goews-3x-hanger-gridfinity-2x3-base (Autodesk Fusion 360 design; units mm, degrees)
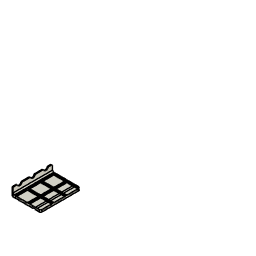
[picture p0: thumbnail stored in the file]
base_feature "Base Feature5"
base_feature "Base Feature1" bodies "Triple Plate Blank"
fillet "Fillet1" radius 3 named "d2_2"
copy_paste_bodies "CutPasteBodies"
align "Align1"
align "Align2"
align "Align3"
move "Move1"
copy_paste_bodies "CopyPasteBodies2"
move "Move2"
copy_paste_bodies "CopyPasteBodies3"
move "Move3"
combine "Combine1" bodies "Grid (1)", "Grid (1) (1)"
sketch "Sketch1" plane through (0, 0, -142.1244) normal (0, 0, -1) x axis (1, 0, 0)
  line L1 (99.15, -104.8) -> (96.15, -104.8)
  line L2 (99.15, 20.8) -> (99.15, -104.8)
  line L3 (96.15, 20.8) -> (99.15, 20.8)
  line L4 (96.15, 15.3) -> (96.15, 20.8)
  line L5 (96.15, -15.3) -> (96.15, 15.3)
  line L6 (96.15, -26.7) -> (96.15, -15.3)
  line L7 (96.15, -57.3) -> (96.15, -26.7)
  line L8 (96.15, -68.7) -> (96.15, -57.3)
  line L9 (96.15, -99.3) -> (96.15, -68.7)
  line L10 (96.15, -104.8) -> (96.15, -99.3)
  line L11 (141.15, -65.8464) -> (107.15, -65.8464)
  line L12 (142.3036, -101) -> (142.3036, -67)
  line L13 (107.15, -102.1536) -> (141.15, -102.1536)
  line L14 (105.9964, -67) -> (105.9964, -101)
  line L15 (141.15, -23.8464) -> (107.15, -23.8464)
  line L16 (142.3036, -59) -> (142.3036, -25)
  line L17 (107.15, -60.1536) -> (141.15, -60.1536)
  line L18 (105.9964, -25) -> (105.9964, -59)
  line L19 (107.15, 21) -> (141.15, 21)
  line L20 (103.15, -17) -> (103.15, 17)
  line L21 (103.15, -59) -> (103.15, -25)
  line L22 (103.15, -101) -> (103.15, -67)
  line L23 (141.15, -105) -> (107.15, -105)
  line L24 (145.15, -67) -> (145.15, -101)
  line L25 (145.15, -25) -> (145.15, -59)
  line L26 (145.15, 17) -> (145.15, -17)
  line L27 (141.15, 18.1536) -> (107.15, 18.1536)
  line L28 (142.3036, -17) -> (142.3036, 17)
  line L29 (107.15, -18.1536) -> (141.15, -18.1536)
  line L30 (105.9964, 17) -> (105.9964, -17)
  line L31 (107.0494, 20.9987) -> (99.15, 20.8)
  line L32 (107.0494, -104.9987) -> (99.15, -104.8)
  arc A1 centre (107.15, -67) radius 1.1536 clockwise from (105.9964, -67) to (107.15, -65.8464)
  arc A2 centre (141.15, -67) radius 1.1536 clockwise from (141.15, -65.8464) to (142.3036, -67)
  arc A3 centre (141.15, -101) radius 1.1536 clockwise from (142.3036, -101) to (141.15, -102.1536)
  arc A4 centre (107.15, -101) radius 1.1536 clockwise from (107.15, -102.1536) to (105.9964, -101)
  arc A5 centre (107.15, -25) radius 1.1536 clockwise from (105.9964, -25) to (107.15, -23.8464)
  arc A6 centre (141.15, -25) radius 1.1536 clockwise from (141.15, -23.8464) to (142.3036, -25)
  arc A7 centre (141.15, -59) radius 1.1536 clockwise from (142.3036, -59) to (141.15, -60.1536)
  arc A8 centre (107.15, -59) radius 1.1536 clockwise from (107.15, -60.1536) to (105.9964, -59)
  arc A9 centre (141.15, 17) radius 4 clockwise from (141.15, 21) to (145.15, 17)
  arc A10 centre (107.15, 17) radius 4 clockwise from (103.15, 17) to (107.15, 21)
  arc A11 centre (107.15, -17) radius 4 clockwise from (107.15, -21) to (103.15, -17)
  arc A12 centre (107.15, -25) radius 4 clockwise from (103.15, -25) to (107.15, -21)
  arc A13 centre (107.15, -59) radius 4 clockwise from (107.15, -63) to (103.15, -59)
  arc A14 centre (107.15, -67) radius 4 clockwise from (103.15, -67) to (107.15, -63)
  arc A15 centre (107.15, -101) radius 4 clockwise from (107.15, -105) to (103.15, -101)
  arc A16 centre (141.15, -101) radius 4 clockwise from (145.15, -101) to (141.15, -105)
  arc A17 centre (141.15, -67) radius 4 clockwise from (141.15, -63) to (145.15, -67)
  arc A18 centre (141.15, -59) radius 4 clockwise from (145.15, -59) to (141.15, -63)
  arc A19 centre (141.15, -25) radius 4 clockwise from (141.15, -21) to (145.15, -25)
  arc A20 centre (141.15, -17) radius 4 clockwise from (145.15, -17) to (141.15, -21)
  arc A21 centre (107.15, 17) radius 1.1536 clockwise from (105.9964, 17) to (107.15, 18.1536)
  arc A22 centre (141.15, 17) radius 1.1536 clockwise from (141.15, 18.1536) to (142.3036, 17)
  arc A23 centre (141.15, -17) radius 1.1536 clockwise from (142.3036, -17) to (141.15, -18.1536)
  arc A24 centre (107.15, -17) radius 1.1536 clockwise from (107.15, -18.1536) to (105.9964, -17)
  point P4 (99.15, 20.8)
  point P68 (99.15, 20.8)
  point P69 (107.0494, 20.9987)
  point P3 (99.15, -104.8)
  point P70 (99.15, -104.8)
  point P71 (107.0494, -104.9987)
  coincident P4 P68
  coincident A10 P69
  tangent A10 L31
  coincident P3 P70
  coincident A15 P71
  tangent A15 L32
extrude "Extrude1" add sketch "Sketch1" profile of L2 A10 L20 A11 A12 L21 A13 A14 L22 A15 L31 L32 against normal blind 4.646 named "d3_1" bodies "Grid"
chamfer "Chamfer1" distance 4 named "d5_1"
sketch "Sketch2" plane through (0, 0, -142.1244) normal (0, 0, -1) x axis (1, 0, 0)
  line L1 (141.15, 18.1536) -> (107.15, 18.1536)
  line L2 (142.3036, -17) -> (142.3036, 17)
  line L3 (107.15, -18.1536) -> (141.15, -18.1536)
  line L4 (105.9964, 17) -> (105.9964, -17)
  line L5 (141.15, -23.8464) -> (107.15, -23.8464)
  line L6 (142.3036, -59) -> (142.3036, -25)
  line L7 (107.15, -60.1536) -> (141.15, -60.1536)
  line L8 (105.9964, -25) -> (105.9964, -59)
  line L9 (141.15, -65.8464) -> (107.15, -65.8464)
  line L10 (142.3036, -101) -> (142.3036, -67)
  line L11 (107.15, -102.1536) -> (141.15, -102.1536)
  line L12 (105.9964, -67) -> (105.9964, -101)
  line L13 (99.15, -104.8) -> (96.15, -104.8)
  line L14 (107.0494, -104.9987) -> (99.15, -104.8)
  line L15 (141.15, -105) -> (107.15, -105)
  line L16 (145.15, -67) -> (145.15, -101)
  line L17 (145.15, -25) -> (145.15, -59)
  line L18 (145.15, 17) -> (145.15, -17)
  line L19 (107.15, 21) -> (141.15, 21)
  line L20 (99.15, 20.8) -> (107.0494, 20.9987)
  line L21 (96.15, 20.8) -> (99.15, 20.8)
  line L22 (96.15, 15.3) -> (96.15, 20.8)
  line L23 (96.15, -15.3) -> (96.15, 15.3)
  line L24 (96.15, -26.7) -> (96.15, -15.3)
  line L25 (96.15, -57.3) -> (96.15, -26.7)
  line L26 (96.15, -68.7) -> (96.15, -57.3)
  line L27 (96.15, -99.3) -> (96.15, -68.7)
  line L28 (96.15, -104.8) -> (96.15, -99.3)
  line L29 (145.15, -25) -> (145.15, -17)
  line L30 (145.15, -67) -> (145.15, -59)
  arc A1 centre (107.15, 17) radius 1.1536 clockwise from (105.9964, 17) to (107.15, 18.1536)
  arc A2 centre (141.15, 17) radius 1.1536 clockwise from (141.15, 18.1536) to (142.3036, 17)
  arc A3 centre (141.15, -17) radius 1.1536 clockwise from (142.3036, -17) to (141.15, -18.1536)
  arc A4 centre (107.15, -17) radius 1.1536 clockwise from (107.15, -18.1536) to (105.9964, -17)
  arc A5 centre (107.15, -25) radius 1.1536 clockwise from (105.9964, -25) to (107.15, -23.8464)
  arc A6 centre (141.15, -25) radius 1.1536 clockwise from (141.15, -23.8464) to (142.3036, -25)
  arc A7 centre (141.15, -59) radius 1.1536 clockwise from (142.3036, -59) to (141.15, -60.1536)
  arc A8 centre (107.15, -59) radius 1.1536 clockwise from (107.15, -60.1536) to (105.9964, -59)
  arc A9 centre (107.15, -67) radius 1.1536 clockwise from (105.9964, -67) to (107.15, -65.8464)
  arc A10 centre (141.15, -67) radius 1.1536 clockwise from (141.15, -65.8464) to (142.3036, -67)
  arc A11 centre (141.15, -101) radius 1.1536 clockwise from (142.3036, -101) to (141.15, -102.1536)
  arc A12 centre (107.15, -101) radius 1.1536 clockwise from (107.15, -102.1536) to (105.9964, -101)
  arc A13 centre (107.15, -101) radius 4 clockwise from (107.15, -105) to (107.0494, -104.9987)
  arc A14 centre (141.15, -101) radius 4 clockwise from (145.15, -101) to (141.15, -105)
  arc A15 centre (141.15, -67) radius 4 clockwise from (141.15, -63) to (145.15, -67)
  arc A16 centre (141.15, -59) radius 4 clockwise from (145.15, -59) to (141.15, -63)
  arc A17 centre (141.15, -25) radius 4 clockwise from (141.15, -21) to (145.15, -25)
  arc A18 centre (141.15, -17) radius 4 clockwise from (145.15, -17) to (141.15, -21)
  arc A19 centre (141.15, 17) radius 4 clockwise from (141.15, 21) to (145.15, 17)
  arc A20 centre (107.15, 17) radius 4 clockwise from (107.0494, 20.9987) to (107.15, 21)
  point P49 (145.15, -17)
  point P62 (145.15, -17)
  point P47 (145.15, -25)
  point P63 (145.15, -25)
  point P46 (145.15, -59)
  point P64 (145.15, -59)
  point P44 (145.15, -67)
  point P65 (145.15, -67)
  coincident P49 P62
  coincident P47 P63
  coincident P46 P64
  coincident P44 P65
extrude "Extrude2" add sketch "Sketch2" profile of A6 A15 A16 A17 A18 L29 L30 against normal blind 4.646 named "d6_1"
move_face "MoveFace1"
move_face "MoveFace2"
sketch "Sketch3" plane through (0, 0, -142.1244) normal (0, 0, -1) x axis (1, 0, 0)
  line L1 (141.15, 18.1536) -> (107.15, 18.1536)
  line L2 (142.3036, -17) -> (142.3036, 17)
  line L3 (107.15, -18.1536) -> (141.15, -18.1536)
  line L4 (105.9964, 17) -> (105.9964, -17)
  line L5 (141.15, -23.8464) -> (107.15, -23.8464)
  line L6 (142.3036, -59) -> (142.3036, -25)
  line L7 (107.15, -60.1536) -> (141.15, -60.1536)
  line L8 (105.9964, -25) -> (105.9964, -59)
  line L9 (141.15, -65.8464) -> (107.15, -65.8464)
  line L10 (142.3036, -101) -> (142.3036, -67)
  line L11 (107.15, -102.1536) -> (141.15, -102.1536)
  line L12 (105.9964, -67) -> (105.9964, -101)
  line L13 (99.15, -104.8) -> (96.15, -104.8)
  line L14 (107.0494, -104.9987) -> (99.15, -104.8)
  line L15 (141.15, -105) -> (107.15, -105)
  line L16 (145.15, 17) -> (145.15, -101)
  line L17 (107.15, 21) -> (141.15, 21)
  line L18 (99.15, 20.8) -> (107.0494, 20.9987)
  line L19 (96.15, 20.8) -> (99.15, 20.8)
  line L20 (96.15, 15.1) -> (96.15, 20.8)
  line L21 (96.15, -15.1) -> (96.15, 15.1)
  line L22 (96.15, -26.9) -> (96.15, -15.1)
  line L23 (96.15, -57.1) -> (96.15, -26.9)
  line L24 (96.15, -68.9) -> (96.15, -57.1)
  line L25 (96.15, -99.1) -> (96.15, -68.9)
  line L26 (96.15, -104.8) -> (96.15, -99.1)
  arc A1 centre (107.15, 17) radius 1.1536 clockwise from (105.9964, 17) to (107.15, 18.1536)
  arc A2 centre (141.15, 17) radius 1.1536 clockwise from (141.15, 18.1536) to (142.3036, 17)
  arc A3 centre (141.15, -17) radius 1.1536 clockwise from (142.3036, -17) to (141.15, -18.1536)
  arc A4 centre (107.15, -17) radius 1.1536 clockwise from (107.15, -18.1536) to (105.9964, -17)
  arc A5 centre (107.15, -25) radius 1.1536 clockwise from (105.9964, -25) to (107.15, -23.8464)
  arc A6 centre (141.15, -25) radius 1.1536 clockwise from (141.15, -23.8464) to (142.3036, -25)
  arc A7 centre (141.15, -59) radius 1.1536 clockwise from (142.3036, -59) to (141.15, -60.1536)
  arc A8 centre (107.15, -59) radius 1.1536 clockwise from (107.15, -60.1536) to (105.9964, -59)
  arc A9 centre (107.15, -67) radius 1.1536 clockwise from (105.9964, -67) to (107.15, -65.8464)
  arc A10 centre (141.15, -67) radius 1.1536 clockwise from (141.15, -65.8464) to (142.3036, -67)
  arc A11 centre (141.15, -101) radius 1.1536 clockwise from (142.3036, -101) to (141.15, -102.1536)
  arc A12 centre (107.15, -101) radius 1.1536 clockwise from (107.15, -102.1536) to (105.9964, -101)
  arc A13 centre (107.15, -101) radius 4 clockwise from (107.15, -105) to (107.0494, -104.9987)
  arc A14 centre (141.15, -101) radius 4 clockwise from (145.15, -101) to (141.15, -105)
  arc A15 centre (141.15, 17) radius 4 clockwise from (141.15, 21) to (145.15, 17)
  arc A16 centre (107.15, 17) radius 4 clockwise from (107.0494, 20.9987) to (107.15, 21)
extrude "Extrude3" add sketch "Sketch3" along normal blind 2.354 named "d8_1"
delete_face "DeleteFace1"
split "Split1" bodies "Triple Plate Blank (1)"
combine "Combine2"
combine "Combine3" bodies "Triple Plate Blank"
chamfer "Chamfer2" distance 4
extrude "Extrude4" cut sketch "Reconstructed-Sketch4" blind -1060
combine "Combine4"
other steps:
base_feature "Base Feature2" bodies "Grid"
base_feature "Base Feature3" bodies "Grid", "Grid (1)"
base_feature "Base Feature4" bodies "Grid (1)", "Grid (1) (1)"
named bodies: "Triple Plate Blank", "Grid", "Grid (1)", "Grid (1) (1)", "Triple Plate Blank (1)"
